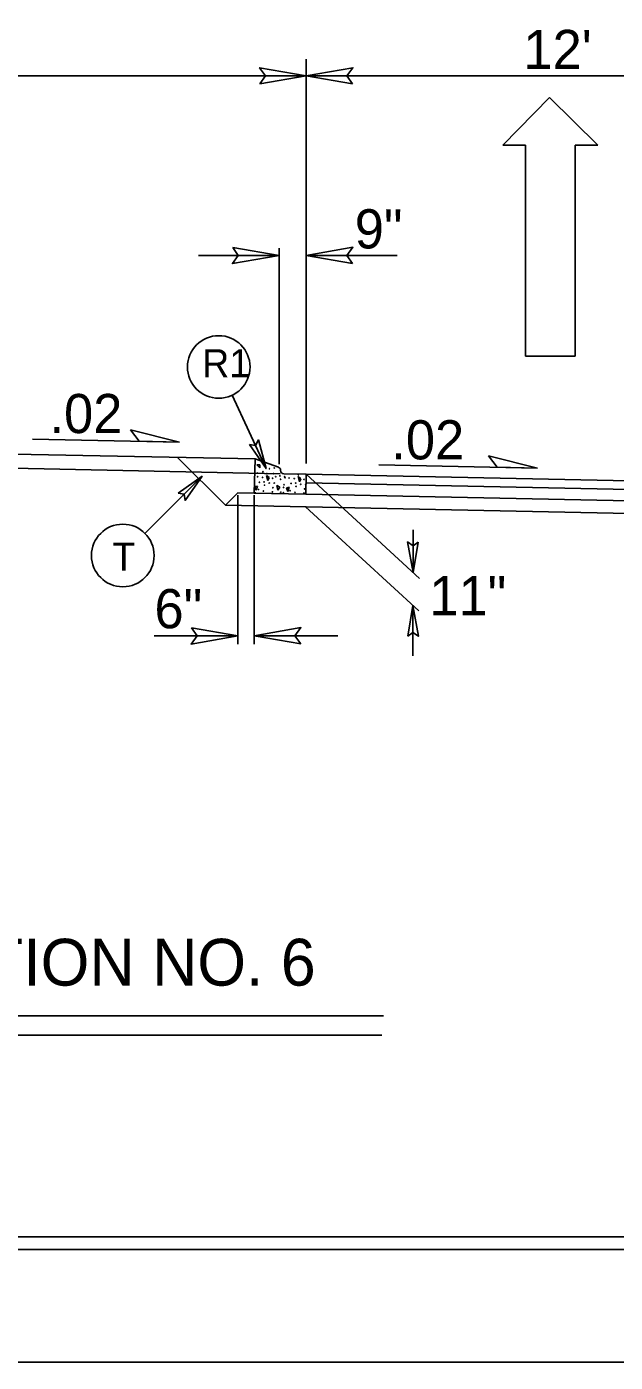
# Model space of a CAD drawing. Extents: x 957297 to 961629, y 830661 to 840840.
# Drawn here: x 959507.1 to 959624.2, y 837206.3 to 837472.1 of the extents above; entities that cross this region are included whole.
import ezdxf

# ---------------------------------------------------------------- set-up
doc = ezdxf.new("R2010")
doc.units = 0
for name, color, linetype in [('Default', 7, 'Continuous'), ('Old_Level_1', 7, 'Continuous'), ('Old_Level_11', 7, 'Continuous'), ('Old_Level_3', 7, 'Continuous'), ('Prop Dimension Text', 7, 'Continuous'), ('Prop Lane Arrow CELL', 7, 'Continuous'), ('Sheet Plot Border Inside CELL', 7, 'Continuous'), ('Sheet Plot Border Outside CELL', 7, 'Continuous'), ('Sheet Typical CELL', 7, 'Continuous'), ('Typical ID Circle CELL', 7, 'Continuous'), ('Typical Terminator CELL', 7, 'Continuous'), ('Typical Text ID Circle CELL', 7, 'Continuous')]:
    doc.layers.add(name, color=color, linetype=linetype)

# ---------------------------------------------------------------- blocks, each defined once
blk = doc.blocks.new('Lane Arrow Through')
at = {"layer": 'Prop Lane Arrow CELL'}
for p, q in [((-3.15, 1.6), (-3.15, 3.1)), ((-3.15, 3.1), (0, 0)), ((-17.15, 1.6), (-3.15, 1.6)), ((-17.15, -1.7), (-17.15, 1.6)), ((0, 0), (-3.15, -3.2)), ((-3.15, -1.7), (-17.15, -1.7)), ((-3.15, -3.2), (-3.15, -1.7))]:
    blk.add_line(p, q, dxfattribs=at)

msp = doc.modelspace()

# ---------------------------------------------------------------- linework, layer by layer
at = {"layer": 'Default'}
for p, q in [((959494.54, 837387.27), (959552.51, 837386.11)), ((959546.62, 837376.89), (959537.09, 837386.42)), ((959494.54, 837384.43), (959557.49, 837383.17))]:
    msp.add_line(p, q, dxfattribs=at)
at = {"layer": 'Old_Level_1'}
for p, q in [((959562.7, 837465.69), (959562.7, 837385.22)), ((959426.38, 837462.34), (959562.7, 837462.34)), ((959562.7, 837462.34), (959656.18, 837462.34)), ((959557.28, 837428.07), (959557.28, 837385.07)), ((959541.25, 837426.62), (959557.28, 837426.62)), ((959562.7, 837426.62), (959580.77, 837426.62)), ((959508.25, 837390.05), (959537.47, 837389.46)), ((959577.12, 837384.92), (959608.72, 837384.29)), ((959562.7, 837383.05), (959782.66, 837378.6)), ((959562.7, 837383.05), (959585.21, 837362.33)), ((959562.67, 837381.32), (959782.66, 837376.87)), ((959549.06, 837379.34), (959546.62, 837376.89)), ((959546.62, 837376.89), (959805.61, 837371.66)), ((959549.06, 837379.34), (959552.36, 837379.28)), ((959549.06, 837349.25), (959549.06, 837378.9)), ((959552.36, 837349.25), (959552.36, 837378.9)), ((959562.62, 837379.07), (959782.66, 837374.62)), ((959562.57, 837376.57), (959585.07, 837355.86)), ((959583.95, 837372), (959583.95, 837363.5)), ((959583.93, 837356.91), (959583.93, 837346.9)), ((959532.46, 837350.89), (959549.06, 837350.89)), ((959552.36, 837350.89), (959568.96, 837350.89)), ((959578.04, 837275.21), (959410.34, 837275.21)), ((959577.76, 837271.41), (959410.06, 837271.41))]:
    msp.add_line(p, q, dxfattribs=at)
at = {"layer": 'Old_Level_11'}
for p, q in [((959529.47, 837389.62), (959527.73, 837391.88)), ((959527.73, 837391.88), (959537.47, 837389.46)), ((959537.47, 837389.46), (959529.47, 837389.62)), ((959600.72, 837384.45), (959598.99, 837386.7)), ((959598.99, 837386.7), (959608.72, 837384.29)), ((959608.72, 837384.29), (959600.72, 837384.45))]:
    msp.add_line(p, q, dxfattribs=at)
at = {"layer": 'Old_Level_3'}
for p, q in [((959552.36, 837379.28), (959552.51, 837386.11)), ((959557.16, 837384.45), (959552.51, 837386.11)), ((959553.49, 837384.92), (959552.9, 837384.93)), ((959552.9, 837384.93), (959553.44, 837384.33)), ((959553.44, 837384.33), (959553.49, 837384.92)), ((959554.8, 837382.82), (959555.06, 837381.79)), ((959555.35, 837382.41), (959554.8, 837382.82)), ((959555.06, 837381.79), (959555.35, 837382.41)), ((959557.59, 837383.8), (959557.59, 837383.83)), ((959562.7, 837383.05), (959558.22, 837383.14)), ((959561.08, 837382.58), (959561.34, 837381.56)), ((959561.63, 837382.17), (959561.08, 837382.58)), ((959561.34, 837381.56), (959561.63, 837382.17)), ((959562.7, 837383.05), (959562.62, 837379.06)), ((959562.62, 837379.06), (959562.7, 837383)), ((959553, 837380.7), (959552.5, 837380.61)), ((959552.5, 837380.61), (959552.73, 837379.86)), ((959552.73, 837379.86), (959553, 837380.7)), ((959556.86, 837380.8), (959557.47, 837380.45)), ((959557.06, 837379.9), (959556.86, 837380.8)), ((959557.47, 837380.45), (959557.06, 837379.9)), ((959559.28, 837380.46), (959558.78, 837380.37)), ((959558.78, 837380.37), (959559.02, 837379.62)), ((959559.02, 837379.62), (959559.28, 837380.46)), ((959562.62, 837379.06), (959552.36, 837379.28))]:
    msp.add_line(p, q, dxfattribs=at)
for centre in [(959553.93, 837385.49), (959552.96, 837383.29), (959553.01, 837382.55), (959554.02, 837382.43), (959554.08, 837383.54), (959554.87, 837383.19), (959555.39, 837384.16), (959556, 837382.27), (959556.17, 837383.19), (959556.32, 837384.3), (959556.62, 837382.56), (959557.46, 837382.73), (959557.6, 837382.05), (959558.38, 837382.56), (959558.49, 837382.36), (959559.29, 837382.31), (959560.3, 837382.19), (959561.15, 837382.95), (959553.2, 837380.01), (959553.38, 837381.46), (959554.18, 837379.71), (959554.31, 837381.53), (959554.39, 837380.88), (959555.33, 837381.29), (959555.97, 837379.55), (959556.08, 837380.38), (959556.32, 837381.3), (959557.64, 837379.48), (959558.16, 837379.38), (959558.18, 837380.43), (959558.3, 837380.97), (959559.48, 837379.77), (959559.67, 837381.22), (959560.46, 837379.47), (959560.6, 837381.29), (959560.67, 837380.64), (959561.61, 837381.05), (959562.28, 837382.03), (959562.36, 837380.14), (959562.6, 837381.06), (959562.25, 837379.31)]:
    msp.add_circle(centre, 0.0434, dxfattribs=at)
for centre, radius, start, end in [((959556.95, 837383.85), 0.641, 358.794, 70.359), ((959558.23, 837383.78), 0.641, 178.794, 268.794), ((959552.6, 837379.31), 0.0434, 25.8325, 153.0355)]:
    msp.add_arc(centre, radius, start, end, dxfattribs=at)
at = {"layer": 'Sheet Plot Border Inside CELL'}
msp.add_lwpolyline([(960390.3, 838283.82), (958723.8, 838283.82), (958723.8, 837228.72), (960390.3, 837228.72)], close=True, dxfattribs=at)
at = {"layer": 'Sheet Plot Border Outside CELL'}
msp.add_lwpolyline([(960394.8, 838306.27), (958710.8, 838306.27), (958710.8, 837206.27), (960394.8, 837206.27)], close=True, dxfattribs=at)
at = {"layer": 'Sheet Typical CELL'}
msp.add_lwpolyline([(960377.8, 838281.27), (958877.8, 838281.27), (958877.8, 837231.27), (960377.8, 837231.27)], close=True, dxfattribs=at)
at = {"layer": 'Typical ID Circle CELL'}
for p, q in [((959547.93, 837398.77), (959554.72, 837384.19)), ((959530.59, 837371.29), (959541.98, 837382.66))]:
    msp.add_line(p, q, dxfattribs=at)
for centre in [(959545.29, 837404.41), (959526.2, 837366.88)]:
    msp.add_circle(centre, 6.23, dxfattribs=at)
at = {"layer": 'Typical Terminator CELL'}
for points in [[(959553.48, 837460.75), (959562.7, 837462.34), (959553.43, 837463.98), (959554.61, 837462.34)], [(959571.92, 837460.75), (959562.7, 837462.34), (959571.98, 837463.98), (959570.8, 837462.34)], [(959548.06, 837428.21), (959557.28, 837426.62), (959548, 837424.98), (959549.18, 837426.62)], [(959571.92, 837425.04), (959562.7, 837426.62), (959571.98, 837428.26), (959570.8, 837426.62)], [(959551.39, 837388.99), (959554.72, 837384.19), (959553.2, 837389.88), (959552.59, 837388.77)], [(959537.2, 837379.29), (959541.98, 837382.66), (959538.6, 837377.84), (959538.4, 837379.08)], [(959584.99, 837369.56), (959583.95, 837363.5), (959582.87, 837369.6), (959583.95, 837368.82)], [(959582.89, 837350.84), (959583.93, 837356.91), (959585.01, 837350.81), (959583.93, 837351.58)], [(959539.84, 837352.48), (959549.06, 837350.89), (959539.79, 837349.25), (959540.97, 837350.89)], [(959561.59, 837349.3), (959552.36, 837350.89), (959561.64, 837352.53), (959560.46, 837350.89)]]:
    msp.add_lwpolyline(points, close=True, dxfattribs=at)

# ---------------------------------------------------------------- block references
at = {"layer": 'Old_Level_1', "xscale": 3, "yscale": 3, "rotation": 90}
msp.add_blockref('Lane Arrow Through', (959611.11, 837458.03), dxfattribs=at)

# ---------------------------------------------------------------- texts
at = {"layer": 'Old_Level_1'}
msp.add_text('TYPICAL SECTION NO. 6', height=9.3239, dxfattribs=at).set_placement((959417.7, 837281.25))
at = {"layer": 'Prop Dimension Text'}
for s, rotation, p in [("12'", 0, (959605.92, 837463.72)), ('9"', 0, (959572.35, 837428.01)), ('.02', 360, (959511.61, 837391.24)), ('.02', 360, (959579.63, 837386.01)), ('11"', 0, (959587.2, 837354.97)), ('6"', 0, (959532.5, 837352.39))]:
    msp.add_text(s, height=7.801, rotation=rotation, dxfattribs=at).set_placement(p)
at = {"layer": 'Typical Text ID Circle CELL'}
for s, height, p in [('R1', 5.572, (959542, 837402.38)), ('T', 5.57, (959524.13, 837363.87))]:
    msp.add_text(s, height=height, dxfattribs=at).set_placement(p)

doc.saveas('drawing.dxf')
